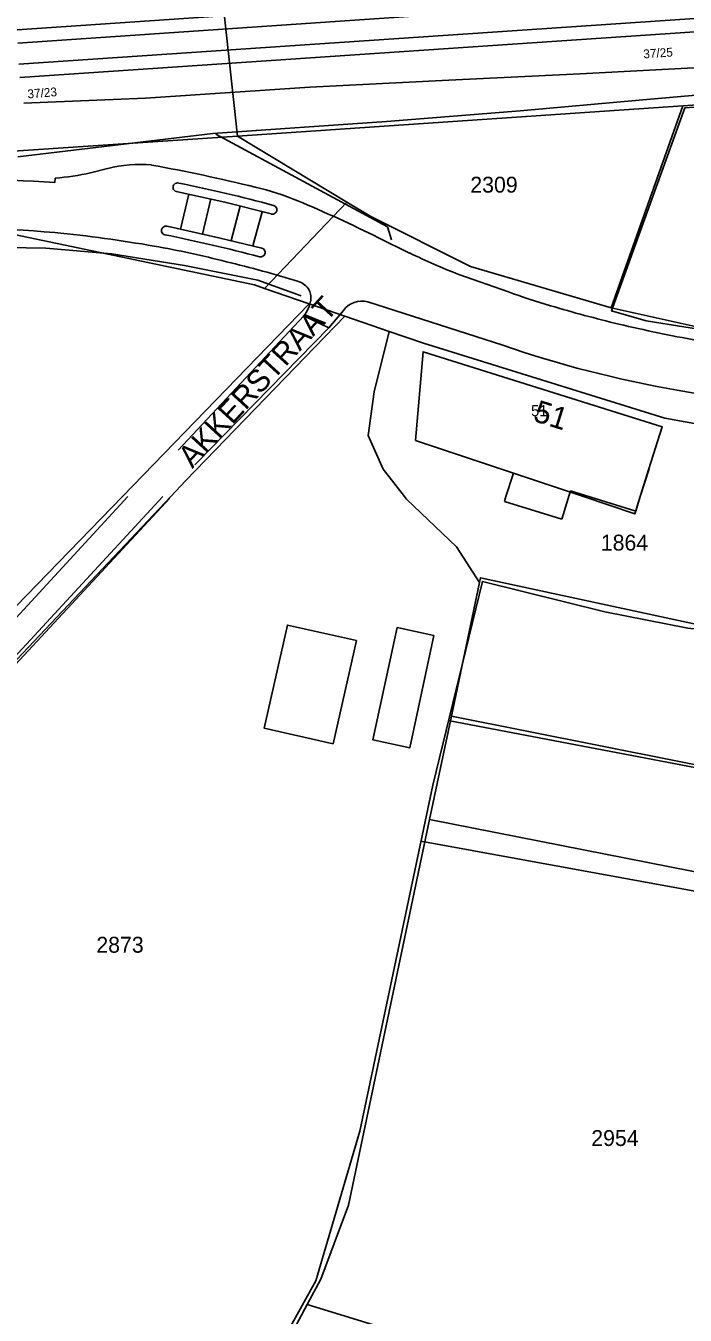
# Model space of a CAD drawing. Extents: x 148816 to 151297, y 399515 to 402500.
# Drawn here: x 149112.9 to 149187.5, y 399907.3 to 400053.3 of the extents above; entities that cross this region are included whole.
import ezdxf

# ---------------------------------------------------------------- set-up
doc = ezdxf.new("R2010")
doc.units = 0
for name, color, linetype in [('B01 Hoofdgebouw  [D] Norm', 7, 'Continuous'), ('B01 Hoofdgebouw  [T] Norm', 7, 'Continuous'), ('B01 hoofgebouw', 7, 'Continuous'), ('B02 Bijgebouw  [D] Norm', 7, 'Continuous'), ('G01 perceelsgrens', 7, 'Continuous'), ('Q01 Spoorrail  [D] Norm', 7, 'Continuous'), ('T04 Haag heg  [D] Gem', 7, 'Continuous'), ('T09 Insteek water  [T] Norm', 7, 'Continuous'), ('V00 Kant verharding algemeen  [T] Norm', 7, 'Continuous'), ('V06 Kant onverhard  [D] Norm', 7, 'Continuous'), ('V06 Kant onverhard  [T] Gem', 7, 'Continuous'), ('Z01 perceelnummer', 7, 'Continuous'), ('Z02 huisnummer', 7, 'Continuous'), ('Z02 Huisnummer  [Tekst] Norm', 7, 'Continuous'), ('Z06 straatnaam', 7, 'Continuous'), ('Z19 Overige Tekst  [Tekst] Gem', 7, 'Continuous')]:
    doc.layers.add(name, color=color, linetype=linetype)

msp = doc.modelspace()

# ---------------------------------------------------------------- linework, layer by layer
at = {"layer": 'B01 Hoofdgebouw  [D] Norm'}
for p, q in [((149168.12, 400002.65), (149161.79, 400004.77)), ((149167.23, 400000), (149168.12, 400002.65)), ((149182.47, 400000), (149183.46, 400003.14)), ((149167.23, 400000), (149167.11, 399999.45)), ((149173.57, 399997.43), (149174.58, 400000.66)), ((149174.58, 400000.66), (149181.95, 399998.35)), ((149181.95, 399998.35), (149182.47, 400000)), ((149167.11, 399999.45), (149173.57, 399997.43))]:
    msp.add_line(p, q, dxfattribs=at)
at = {"layer": 'B01 Hoofdgebouw  [T] Norm'}
for p, q in [((149157.89, 400016.39), (149157.04, 400006.36)), ((149184.95, 400007.91), (149157.89, 400016.39)), ((149183.45, 400003.14), (149184.95, 400007.91)), ((149157.04, 400006.36), (149161.79, 400004.77))]:
    msp.add_line(p, q, dxfattribs=at)
at = {"layer": 'B01 hoofgebouw'}
for points in [[(149183.45, 400003.14), (149184.95, 400007.91), (149157.89, 400016.39), (149157.04, 400006.36), (149161.79, 400004.77)], [(149161.79, 400004.77), (149176.04, 400000)], [(149182.46, 400000), (149183.45, 400003.14)], [(149176.04, 400000), (149181.85, 399998.06), (149182.46, 400000)]]:
    msp.add_lwpolyline(points, dxfattribs=at)
at = {"layer": 'B02 Bijgebouw  [D] Norm'}
for points in [[(149150.33, 399983.7), (149147.69, 399972.01), (149139.89, 399973.77), (149142.53, 399985.45)], [(149159.11, 399984.26), (149156.38, 399971.53), (149152.2, 399972.43), (149154.93, 399985.16)]]:
    msp.add_lwpolyline(points, close=True, dxfattribs=at)
at = {"layer": 'G01 perceelsgrens'}
for points in [[(149134.62, 400061.65), (149136.89, 400040.82)], [(149187.27, 400044.24), (149270.68, 400049.9)], [(149136.89, 400040.82), (149187.27, 400044.24)], [(149179.17, 400021.39), (149187.27, 400044.24)], [(149000, 400031.55), (149069.23, 400036.3), (149136.89, 400040.82)], [(149136.89, 400040.82), (149149.26, 400033.35)], [(149149.26, 400033.35), (149139.94, 400023.57)], [(149149.26, 400033.35), (149151.95, 400031.72), (149163.26, 400026.07), (149179.17, 400021.39)], [(149013.85, 400026.68), (149069.84, 400030.55), (149070.05, 400028.58), (149109.22, 400030.17), (149138.8, 400023.96)], [(149138.8, 400023.96), (149139.94, 400023.57)], [(149139.94, 400023.57), (149144.99, 400021.83)], [(149123.85, 400000), (149144.99, 400021.83)], [(149144.99, 400021.83), (149149.03, 400020.43)], [(149129.32, 400000), (149130.98, 400001.77), (149149.03, 400020.43)], [(149149.03, 400020.43), (149154.04, 400018.7)], [(149179.17, 400021.39), (149189.68, 400019.05), (149200.07, 400017.39), (149227.27, 400015.92), (149245, 400016.38)], [(149155.77, 400000), (149153.38, 400003.1), (149151.65, 400006.92), (149152.36, 400011.86), (149154.04, 400018.7)], [(149154.04, 400018.7), (149157.93, 400017.36), (149185.23, 400008.87), (149194.46, 400007.2)], [(149067.71, 399932.27), (149083.7, 399949.33), (149091.88, 399960.36), (149129.32, 400000)], [(149100.89, 399975.19), (149102.47, 399977.01), (149111.78, 399987.53), (149123.85, 400000)], [(149164.27, 399990.28), (149161.66, 399994.3), (149155.99, 399999.71), (149155.77, 400000)], [(149161.08, 399975.13), (149164.27, 399990.28)], [(149164.27, 399990.28), (149164.38, 399990.8), (149191.71, 399984.92), (149192.36, 399984.86)], [(149158.62, 399963.44), (149161.08, 399975.13)], [(149161.08, 399975.13), (149202.99, 399966.79), (149216, 399967.35), (149219.96, 399966.48), (149228.2, 399967.87), (149228.24, 399967.66), (149236.85, 399969.15)], [(149144.76, 399908.49), (149146.3, 399911.38), (149149.43, 399919.73), (149158.62, 399963.44)], [(149158.62, 399963.44), (149198.25, 399955.6), (149199.45, 399951.15)], [(149134.38, 399888.99), (149144.76, 399908.49)], [(149144.76, 399908.49), (149180.42, 399897.54), (149200.38, 399891.4)]]:
    msp.add_lwpolyline(points, dxfattribs=at)
at = {"layer": 'Q01 Spoorrail  [D] Norm'}
for p, q in [((149244.15, 400061.92), (149111.93, 400052.84)), ((149244.25, 400060.42), (149112.03, 400051.34)), ((149112.13, 400048.95), (149244.3, 400057.93)), ((149112.23, 400047.45), (149244.4, 400056.43))]:
    msp.add_line(p, q, dxfattribs=at)
at = {"layer": 'T04 Haag heg  [D] Gem'}
for p, q in [((149134.43, 400041.03), (149153.86, 400030.55)), ((149153.86, 400030.55), (149154.31, 400029.07))]:
    msp.add_line(p, q, dxfattribs=at)
for points in [[(149314.94, 400017.04), (149245.48, 400016.34), (149237.91, 400016.24), (149230.04, 400015.98), (149222.5, 400015.84), (149202.77, 400017.12), (149191.67, 400018.53), (149183.14, 400019.89), (149179.21, 400021.03), (149187.49, 400044.02), (149270.43, 400049.77), (149310.47, 400052.09), (149317.8, 400052.32), (149348.48, 400052.76)], [(149144.09, 400022.73), (149139.16, 400024.52), (149130.86, 400026.17), (149122.61, 400027.5), (149115.17, 400028.13), (149097.21, 400028.45), (149090.28, 400028.24), (149078.4, 400027.87), (149064.85, 400027.07), (149050.68, 400026.07), (149035.24, 400025.15), (149000, 400022.76)], [(149129.2, 399999.81), (149093.76, 399961.63), (149061.87, 399926.52), (149022.94, 399883.66), (149092.07, 399821.42)], [(149200.91, 399983.71), (149187.83, 399985.1), (149178.47, 399986.95), (149164.59, 399990.38), (149158.98, 399967.33), (149150.74, 399928.13), (149145.74, 399911.16), (149116.3, 399858.08), (149092.09, 399821.44), (149085.02, 399809.57), (149074.52, 399794.43), (149051.65, 399749.82)], [(149160.71, 399974.64), (149207.86, 399965.66)], [(149250.73, 399903.88), (149209.34, 399896.54), (149199.21, 399953.38), (149157.62, 399960.98)]]:
    msp.add_lwpolyline(points, dxfattribs=at)
at = {"layer": 'T09 Insteek water  [T] Norm'}
for points in [[(149269.82, 400054.28), (149254.74, 400053.28), (149229.83, 400051.54), (149208.18, 400049.97), (149192.79, 400048.79), (149175.65, 400047.89), (149160.8, 400047.17), (149145.08, 400046.37), (149126.45, 400045.13), (149112.68, 400044.54)], [(149112, 400038.49), (149134.1, 400041.13), (149153.75, 400042.47), (149168.88, 400043.67), (149182.33, 400044.9), (149193.05, 400045.85), (149203.1, 400046.49), (149216.61, 400047.34), (149232.14, 400048.34), (149247.66, 400049.47), (149261.92, 400050.52), (149273.22, 400051.37), (149284.72, 400052.27), (149300.29, 400053.45)]]:
    msp.add_lwpolyline(points, dxfattribs=at)
at = {"layer": 'V00 Kant verharding algemeen  [T] Norm'}
for points in [[(149120.23, 400036.68), (149122.18, 400037.16)], [(149116.19, 400035.55), (149116.24, 400036.06)], [(149140.68, 400032), (149135.45, 400033.35), (149129.95, 400034.53)], [(149139.64, 400028.14), (149134.77, 400029.31), (149128.91, 400030.61)], [(149152.82, 400029.31), (149156.36, 400027.58)], [(149161.91, 400025.15), (149167.54, 400023.17)], [(149166.9, 400017.13), (149151.63, 400022.04)], [(149148.86, 400021.06), (149147.22, 400019.11), (149144.39, 400020.47)], [(149211.92, 400008.29), (149199.56, 400009.95), (149191.34, 400011.21), (149186.65, 400012.04)]]:
    msp.add_lwpolyline(points, dxfattribs=at)
for centre, radius, start, end in [((149125.83, 400022.66), 14.95, 84.942, 104.1288), ((149089.55, 399832.67), 208.3, 76.2997, 79.6008), ((149114, 400063.5), 27.54, 274.6824, 283.0842), ((149102.26, 399831.26), 204.77, 86.0991, 91.4613), ((149130.08, 400035.02), 0.5, 73.9067, 255.8244), ((149099.18, 399879.72), 158.84, 74.7531, 78.7319), ((149131.35, 400003.41), 32.52, 67.6698, 76.5985), ((149087.28, 399898.53), 146.28, 63.3827, 67.3135), ((149140.83, 400032.48), 0.503, 252.9383, 75.922), ((149101.35, 399843.67), 186.82, 85.4435, 91.3126), ((149128.77, 400030.13), 0.499, 74.1229, 256.5243), ((149098.25, 399857.11), 173.73, 80.3246, 84.0733), ((149091.85, 399847.08), 186.24, 75.217, 78.6041), ((149106.8, 399913.34), 116.87, 75.724, 79.8222), ((149139.5, 400027.65), 0.513, 255.6883, 74.3985), ((149186.34, 400088.63), 68.01, 243.8437, 248.9495), ((149096.92, 399868.43), 162.83, 73.2724, 76.253), ((149143.06, 400022.29), 2.2, 29.7409, 70.648), ((149143.27, 400022.52), 1.92, 345.6564, 26.9959), ((149204.52, 400128.64), 111.77, 250.6777, 253.2421), ((149141.52, 400022.76), 3.67, 321.3772, 348.7364), ((149150.95, 400019.55), 2.58, 74.6653, 144.1065), ((149217.06, 400171.85), 156.76, 253.408, 256.3399), ((149220.79, 400193.22), 178.41, 256.7955, 259.6964), ((149208.53, 400138.04), 127.88, 251.0003, 260.1506)]:
    msp.add_arc(centre, radius, start, end, dxfattribs=at)
at = {"layer": 'V06 Kant onverhard  [D] Norm'}
for points in [[(149131.38, 400034.23), (149130.44, 400030.27)], [(149132.9, 400029.73), (149133.86, 400033.7)], [(149137.19, 400032.9), (149136.17, 400028.98)], [(149138.62, 400028.39), (149139.66, 400032.26)], [(149128.43, 400000), (149097.04, 399966.02), (149069.46, 399935.99), (149046.98, 399911.33), (149019.09, 399880.8), (149000, 399859.11)], [(149124.48, 400000), (149097.77, 399971.05), (149081.8, 399953.84), (149064.42, 399935.02), (149046.22, 399914.98), (149038.62, 399906.78), (149020.25, 399886.67), (149007.01, 399871.16), (149000, 399862.91)]]:
    msp.add_lwpolyline(points, dxfattribs=at)
at = {"layer": 'V06 Kant onverhard  [T] Gem'}
for p, q in [((149130.17, 400005.24), (149144.39, 400020.47)), ((149147.22, 400019.11), (149132.06, 400003.61))]:
    msp.add_line(p, q, dxfattribs=at)

# ---------------------------------------------------------------- texts
at = {"layer": 'Z01 perceelnummer'}
for s, p in [('2309', (149163.23, 400034.42)), ('1864', (149178, 399993.88)), ('2873', (149120.9, 399948.34)), ('2954', (149176.92, 399926.45))]:
    msp.add_text(s, height=1.8, dxfattribs=at).set_placement(p)
at = {"layer": 'Z02 huisnummer'}
msp.add_text('51', height=2.5, rotation=342.5981, dxfattribs=at).set_placement((149170.23, 400008.59))
at = {"layer": 'Z02 Huisnummer  [Tekst] Norm'}
msp.add_text('37/23', height=1, rotation=4.4334, dxfattribs=at).set_placement((149113.14, 400045.09))
msp.add_text('51', height=1.25, dxfattribs=at).set_placement((149170.1, 400009.1))
at = {"layer": 'Z06 straatnaam'}
msp.add_text('AKKERSTRAAT', height=2.5, rotation=47.5529, dxfattribs=at).set_placement((149131.77, 400003.11))
at = {"layer": 'Z19 Overige Tekst  [Tekst] Gem'}
msp.add_text('37/25', height=1, rotation=3.8158, dxfattribs=at).set_placement((149182.84, 400049.62))

doc.saveas('drawing.dxf')
